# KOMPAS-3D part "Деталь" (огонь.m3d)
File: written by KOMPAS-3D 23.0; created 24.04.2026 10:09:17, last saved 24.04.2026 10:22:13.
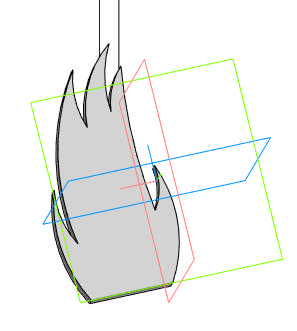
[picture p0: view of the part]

Document properties: Автор: USER; Полное имя файла: C:\Users\USER\Desktop\огонь.m3d

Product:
- Part/product: Деталь
    Масса: 0.035009

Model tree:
1. Эскиз:1
2. Элемент выдавливания:1
     Расстояние 1 = 4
